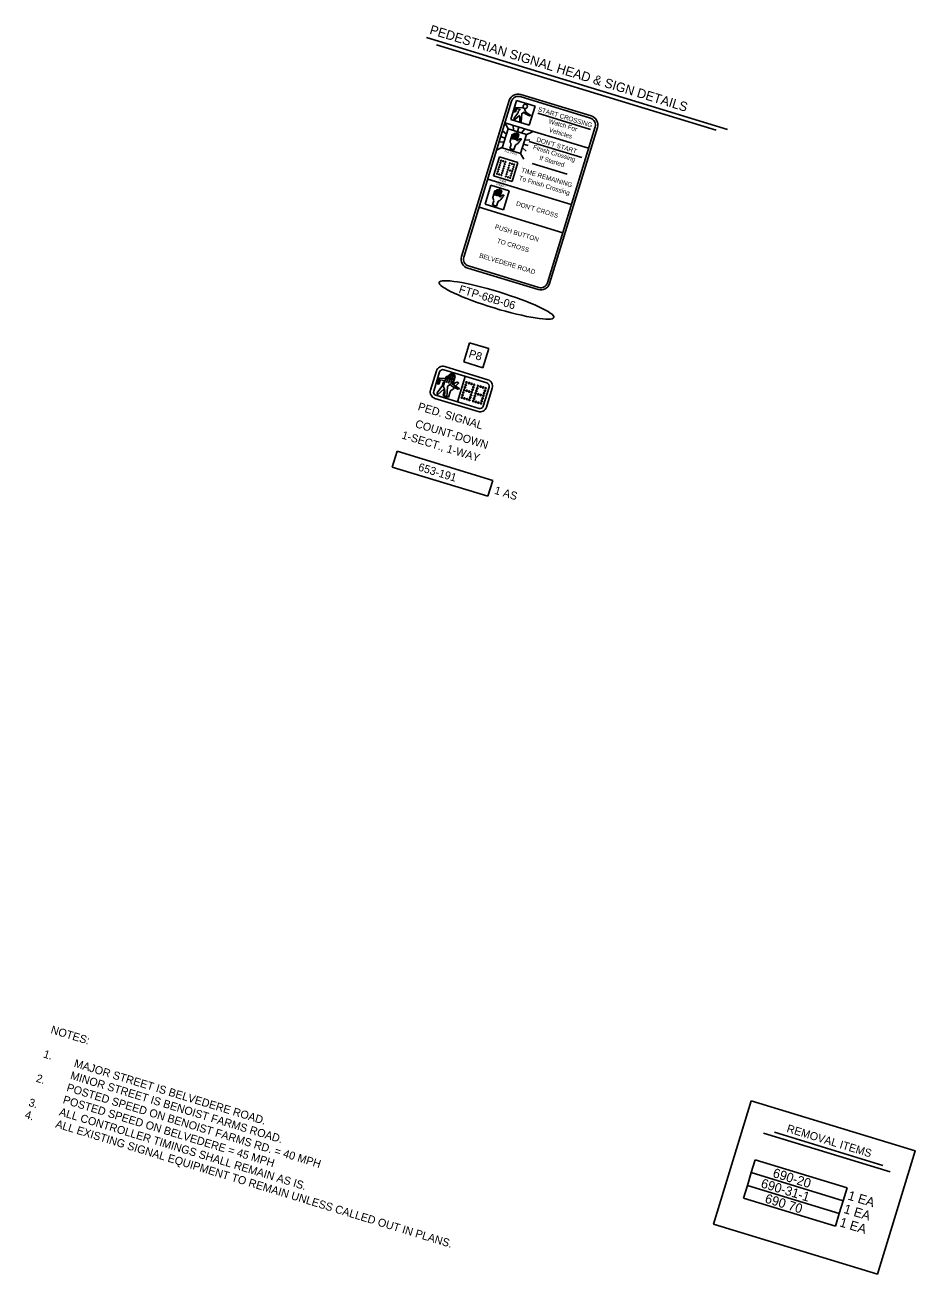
# Model space of a CAD drawing. Extents: x 925415 to 926090, y 857813 to 858332.
import ezdxf

# ---------------------------------------------------------------- set-up
doc = ezdxf.new("R2010")
doc.units = 0
for name, color, linetype in [('PayItem_dp', 7, 'Continuous'), ('PedHead', 7, 'Continuous'), ('SignalHead', 7, 'Continuous'), ('SignalSOP', 7, 'Continuous'), ('SignPanel', 7, 'Continuous'), ('SumBoxLines_dp', 7, 'Continuous'), ('TextMisc', 7, 'Continuous'), ('TextNotes', 7, 'Continuous'), ('TextTables', 7, 'Continuous')]:
    doc.layers.add(name, color=color, linetype=linetype)

msp = doc.modelspace()

# ---------------------------------------------------------------- linework, layer by layer
at = {"layer": 'PayItem_dp'}
msp.add_ellipse((925555.93, 858249.83), major_axis=(17.21, -5.26), ratio=0.138889, dxfattribs=at)
at = {"layer": 'PedHead'}
for p, q in [((925546.11, 858231.24), (925547.87, 858236.97)), ((925547.87, 858236.97), (925553.61, 858235.22)), ((925553.61, 858235.22), (925551.85, 858229.48)), ((925551.85, 858229.48), (925546.11, 858231.24)), ((925546.59, 858226.91), (925544.25, 858219.26))]:
    msp.add_line(p, q, dxfattribs=at)
for points in [[(925537.93, 858228.52), (925536.17, 858222.78)], [(925538.88, 858228.22), (925537.13, 858222.49)], [(925553.04, 858224.94), (925540.13, 858228.89)], [(925540.42, 858229.84), (925553.33, 858225.89)], [(925551.95, 858217.95), (925553.7, 858223.69)], [(925537.5, 858220.28), (925550.41, 858216.33)], [(925537.79, 858221.24), (925550.7, 858217.29)], [(925552.9, 858217.66), (925554.66, 858223.4)]]:
    msp.add_lwpolyline(points, dxfattribs=at)
for points in [[(925539.91, 858221.22), (925540.3, 858222.52), (925540.39, 858222.78), (925540.4, 858223.11), (925540.35, 858223.21), (925540.28, 858223.4), (925540.13, 858223.58), (925540.1, 858223.75), (925540.06, 858224.05), (925540.09, 858224.13), (925540.89, 858226.77), (925541.03, 858226.81), (925541.07, 858226.93), (925541.23, 858226.92), (925541.34, 858226.84), (925541.42, 858226.7), (925541.4, 858226.66), (925541, 858225.07), (925541.64, 858227.17), (925541.78, 858227.34), (925542.02, 858227.3), (925542.1, 858227.28), (925542.23, 858227.03), (925541.57, 858224.89), (925542.44, 858227.3), (925542.57, 858227.47), (925542.66, 858227.49), (925542.89, 858227.42), (925542.94, 858227.32), (925542.91, 858227.2), (925542.24, 858224.73), (925542.93, 858226.99), (925543.09, 858227.1), (925543.21, 858227.11), (925543.38, 858227.1), (925543.47, 858226.99), (925543.55, 858226.84), (925542.85, 858224.54), (925542.82, 858224.47), (925542.89, 858224.4), (925542.98, 858224.42), (925542.98, 858224.42), (925543.56, 858224.95), (925543.84, 858225.03), (925543.85, 858225.07), (925543.94, 858225.09), (925544.04, 858225.14), (925544.16, 858225.14), (925544.43, 858225.06), (925544.53, 858224.99), (925544.51, 858224.91), (925544.5, 858224.87), (925544.49, 858224.84), (925544.47, 858224.8), (925544.05, 858224.38), (925543.19, 858223.35), (925543.02, 858223.19), (925542.77, 858222.93), (925542.62, 858222.85), (925542.39, 858222.76), (925542.26, 858222.63), (925542.03, 858222.28), (925541.55, 858220.71)], [(925542.32, 858226.08), (925541.7, 858226.27), (925538.82, 858226.4), (925538.2, 858224.67), (925538.68, 858224.6), (925539.18, 858225.83), (925540.58, 858225.61), (925540.45, 858225.44), (925540.27, 858225.29), (925539.88, 858224.95), (925539.82, 858224.76), (925539.85, 858224.58), (925539.79, 858224.39), (925539.73, 858224.2), (925539.72, 858224.16), (925538.13, 858221.97), (925538.23, 858221.35), (925540.26, 858223.2), (925540.46, 858222.47), (925540.4, 858220.65), (925541.07, 858220.65), (925541.16, 858222.3), (925541.23, 858223.91), (925542.01, 858224.55), (925542.51, 858223.98), (925544.32, 858223.05), (925544.84, 858223.14), (925542.95, 858224.47), (925542.54, 858225.43), (925542.56, 858225.51), (925542.47, 858225.62), (925542.47, 858225.62)]]:
    msp.add_lwpolyline(points, close=True, dxfattribs=at)
for centre, radius in [((925542.62, 858226.85), 0.87), ((925546.49, 858223.6), 0.2), ((925546.72, 858224.36), 0.2), ((925546.95, 858225.13), 0.2), ((925547.72, 858224.89), 0.2), ((925548.48, 858224.66), 0.2), ((925549.01, 858223.66), 0.2), ((925549.25, 858224.42), 0.2), ((925550.4, 858224.07), 0.2), ((925551.16, 858223.84), 0.2), ((925551.93, 858223.61), 0.2), ((925552.69, 858223.37), 0.2), ((925545.55, 858220.54), 0.2), ((925545.78, 858221.3), 0.2), ((925546.02, 858222.07), 0.2), ((925546.25, 858222.83), 0.2), ((925546.31, 858220.3), 0.2), ((925547.02, 858222.6), 0.2), ((925547.08, 858220.07), 0.2), ((925547.78, 858222.36), 0.2), ((925547.84, 858219.83), 0.2), ((925548.08, 858220.6), 0.2), ((925548.31, 858221.36), 0.2), ((925548.55, 858222.13), 0.2), ((925548.78, 858222.89), 0.2), ((925549.23, 858220.25), 0.2), ((925549.46, 858221.01), 0.2), ((925549.69, 858221.78), 0.2), ((925549.93, 858222.54), 0.2), ((925550.16, 858223.31), 0.2), ((925550.46, 858221.54), 0.2), ((925551.22, 858221.31), 0.2), ((925551.76, 858220.31), 0.2), ((925551.99, 858221.08), 0.2), ((925552.22, 858221.84), 0.2), ((925552.46, 858222.61), 0.2), ((925548.99, 858219.48), 0.2), ((925549.76, 858219.25), 0.2), ((925550.52, 858219.02), 0.2), ((925551.29, 858218.78), 0.2), ((925551.52, 858219.55), 0.2)]:
    msp.add_circle(centre, radius, dxfattribs=at)
for centre, radius, start, end in [((925539.84, 858227.93), 2, 72.9928, 162.9928), ((925539.84, 858227.93), 1, 72.9928, 162.9928), ((925552.75, 858223.98), 1, 342.9928, 72.9928), ((925552.75, 858223.98), 2, 342.9928, 72.9928), ((925538.08, 858222.19), 2, 162.9928, 252.9928), ((925538.08, 858222.19), 1, 162.9928, 252.9928), ((925550.99, 858218.24), 2, 252.9928, 342.9928), ((925550.99, 858218.24), 1, 252.9928, 342.9928)]:
    msp.add_arc(centre, radius, start, end, dxfattribs=at)
at = {"layer": 'SignalHead'}
for p, q in [((925632.31, 857988.08), (925633.48, 857991.91)), ((925633.48, 857991.91), (925661.02, 857983.5)), ((925631.14, 857984.26), (925632.31, 857988.08)), ((925659.86, 857979.67), (925632.31, 857988.08)), ((925632.31, 857988.08), (925659.86, 857979.67)), ((925629.98, 857980.43), (925631.14, 857984.26)), ((925658.69, 857975.85), (925631.14, 857984.26)), ((925631.14, 857984.26), (925658.69, 857975.85)), ((925657.52, 857972.02), (925629.98, 857980.43)), ((925661.02, 857983.5), (925659.86, 857979.67)), ((925659.86, 857979.67), (925658.69, 857975.85)), ((925658.69, 857975.85), (925657.52, 857972.02))]:
    msp.add_line(p, q, dxfattribs=at)
at = {"layer": 'SignalSOP'}
for p, q in [((925635.94, 857999.93), (925673.96, 857988.32)), ((925639.23, 858000.18), (925671.75, 857990.25))]:
    msp.add_line(p, q, dxfattribs=at)
at = {"layer": 'SignPanel'}
for p, q in [((925563.02, 858310.81), (925584.13, 858304.36)), ((925563.22, 858311.47), (925584.34, 858305.02)), ((925545.47, 858262.83), (925559.77, 858309.63)), ((925546.13, 858262.62), (925560.43, 858309.43)), ((925561.98, 858309.62), (925560.24, 858303.92)), ((925558.46, 858302.97), (925583.53, 858295.31)), ((925558.49, 858302.96), (925559.4, 858301.18)), ((925561.03, 858300.68), (925560.91, 858302.22)), ((925568.34, 858305.81), (925584.12, 858300.99)), ((925557.19, 858298.81), (925558.54, 858298.37)), ((925557.71, 858300.53), (925558.9, 858299.52)), ((925559.4, 858301.18), (925564.92, 858299.49)), ((925562.21, 858300.32), (925562.65, 858301.69)), ((925564.92, 858299.49), (925563.18, 858293.79)), ((925563.4, 858299.96), (925564.41, 858301.15)), ((925564.87, 858299.31), (925566.77, 858300.28)), ((925585.51, 858301.77), (925571.21, 858254.96)), ((925586.17, 858301.57), (925571.87, 858254.76)), ((925555.95, 858294.75), (925557.71, 858295.65)), ((925556.67, 858297.11), (925558.2, 858297.23)), ((925563.18, 858293.79), (925557.66, 858295.48)), ((925563.69, 858295.44), (925564.87, 858294.44)), ((925564.04, 858296.6), (925565.4, 858296.16)), ((925564.39, 858297.73), (925565.91, 858297.86)), ((925565.76, 858297.36), (925581.54, 858292.54)), ((925556.82, 858292.73), (925562.34, 858291.04)), ((925562.34, 858291.04), (925560.6, 858285.34)), ((925563.18, 858293.79), (925564.09, 858292.01)), ((925566.63, 858290.75), (925577.12, 858287.54)), ((925553.3, 858286.07), (925578.37, 858278.41)), ((925554.24, 858284.28), (925559.76, 858282.6)), ((925560.6, 858285.34), (925555.08, 858287.03)), ((925559.76, 858282.6), (925558.02, 858276.9)), ((925550.72, 858277.63), (925575.79, 858269.97)), ((925558.02, 858276.9), (925552.5, 858278.58)), ((925568.42, 858252.93), (925547.31, 858259.38)), ((925568.63, 858253.59), (925547.51, 858260.04))]:
    msp.add_line(p, q, dxfattribs=at)
for points in [[(925564.31, 858307.29), (925563.89, 858307.42), (925561.74, 858307.55), (925561.23, 858306.27), (925561.63, 858306.26), (925561.96, 858307.14), (925563.01, 858306.99), (925562.91, 858306.85), (925562.8, 858306.71), (925562.5, 858306.46), (925562.45, 858306.3), (925562.47, 858306.18), (925562.44, 858306.07), (925562.39, 858305.91), (925562.37, 858305.86), (925561.19, 858304.26), (925561.29, 858303.82), (925562.79, 858305.15), (925562.91, 858304.6), (925562.91, 858303.27), (925563.36, 858303.25), (925563.45, 858304.49), (925563.53, 858305.68), (925564.13, 858306.13), (925564.47, 858305.74), (925565.83, 858305.09), (925566.2, 858305.15), (925564.76, 858306.11), (925564.46, 858306.84), (925564.49, 858306.94), (925564.44, 858306.96), (925564.44, 858306.96)], [(925559.93, 858295.23), (925560.22, 858296.18), (925560.3, 858296.45), (925560.25, 858296.64), (925560.28, 858296.74), (925560.21, 858296.88), (925560.08, 858297.04), (925560.06, 858297.16), (925560, 858297.35), (925560.03, 858297.45), (925560.63, 858299.41), (925560.77, 858299.48), (925560.77, 858299.48), (925560.94, 858299.48), (925560.98, 858299.42), (925561.09, 858299.38), (925561.07, 858299.33), (925560.7, 858298.12), (925561.18, 858299.7), (925561.34, 858299.83), (925561.5, 858299.78), (925561.55, 858299.76), (925561.67, 858299.61), (925561.17, 858297.97), (925561.78, 858299.75), (925561.88, 858299.89), (925562, 858299.91), (925562.16, 858299.86), (925562.19, 858299.8), (925562.16, 858299.69), (925561.67, 858297.88), (925562.18, 858299.57), (925562.25, 858299.6), (925562.37, 858299.63), (925562.55, 858299.63), (925562.57, 858299.51), (925562.66, 858299.42), (925562.14, 858297.73), (925562.11, 858297.63), (925562.11, 858297.63), (925562.21, 858297.6), (925562.21, 858297.6), (925562.69, 858298.03), (925562.83, 858298.1), (925562.85, 858298.15), (925562.91, 858298.19), (925563.02, 858298.16), (925563.09, 858298.19), (925563.3, 858298.13), (925563.34, 858298.06), (925563.34, 858298.06), (925563.32, 858298.01), (925563.3, 858297.96), (925563.29, 858297.9), (925563.03, 858297.63), (925562.39, 858296.85), (925562.29, 858296.71), (925562.07, 858296.54), (925561.93, 858296.47), (925561.74, 858296.41), (925561.71, 858296.31), (925561.52, 858296.08), (925561.15, 858294.86)], [(925554.77, 858278.34), (925555.06, 858279.29), (925555.14, 858279.55), (925555.09, 858279.74), (925555.12, 858279.85), (925555.05, 858279.99), (925554.92, 858280.14), (925554.9, 858280.26), (925554.84, 858280.45), (925554.87, 858280.56), (925555.47, 858282.51), (925555.61, 858282.59), (925555.61, 858282.59), (925555.78, 858282.59), (925555.82, 858282.52), (925555.93, 858282.49), (925555.91, 858282.44), (925555.54, 858281.22), (925556.02, 858282.81), (925556.18, 858282.93), (925556.33, 858282.88), (925556.39, 858282.87), (925556.51, 858282.71), (925556.01, 858281.08), (925556.61, 858282.86), (925556.72, 858283), (925556.84, 858283.02), (925557, 858282.97), (925557.03, 858282.9), (925557, 858282.8), (925556.5, 858280.99), (925557.02, 858282.67), (925557.09, 858282.71), (925557.21, 858282.73), (925557.39, 858282.74), (925557.41, 858282.61), (925557.5, 858282.53), (925556.98, 858280.84), (925556.95, 858280.73), (925556.95, 858280.73), (925557.05, 858280.7), (925557.05, 858280.7), (925557.53, 858281.13), (925557.67, 858281.21), (925557.69, 858281.26), (925557.75, 858281.3), (925557.86, 858281.26), (925557.93, 858281.3), (925558.14, 858281.24), (925558.18, 858281.17), (925558.18, 858281.17), (925558.16, 858281.11), (925558.14, 858281.06), (925558.13, 858281.01), (925557.87, 858280.74), (925557.23, 858279.96), (925557.13, 858279.81), (925556.91, 858279.65), (925556.77, 858279.58), (925556.58, 858279.52), (925556.54, 858279.41), (925556.36, 858279.18), (925555.99, 858277.97)]]:
    msp.add_lwpolyline(points, close=True, dxfattribs=at)
for points in [[(925567.5, 858307.94), (925561.98, 858309.62)], [(925565.76, 858302.24), (925567.5, 858307.94)], [(925560.24, 858303.92), (925565.76, 858302.24)], [(925559.4, 858301.18), (925557.66, 858295.48)], [(925556.82, 858292.73), (925555.08, 858287.03)], [(925554.24, 858284.28), (925552.5, 858278.58)]]:
    msp.add_lwpolyline(points, dxfattribs=at)
for centre, radius in [((925564.55, 858307.89), 0.648), ((925557.1, 858290.96), 0.138), ((925557.31, 858291.62), 0.138), ((925557.97, 858291.42), 0.138), ((925558.63, 858291.22), 0.138), ((925556.1, 858287.66), 0.138), ((925556.3, 858288.32), 0.138), ((925556.5, 858288.98), 0.138), ((925556.7, 858289.64), 0.138), ((925556.76, 858287.46), 0.138), ((925556.9, 858290.3), 0.138), ((925557.42, 858287.26), 0.138), ((925557.62, 858287.92), 0.138), ((925557.82, 858288.58), 0.138), ((925558.02, 858289.24), 0.138), ((925558.22, 858289.9), 0.138), ((925558.42, 858290.56), 0.138), ((925558.94, 858287.51), 0.138), ((925559.14, 858288.17), 0.138), ((925559.34, 858288.83), 0.138), ((925559.54, 858289.49), 0.138), ((925559.74, 858290.15), 0.138), ((925559.94, 858290.81), 0.138), ((925560, 858288.63), 0.138), ((925560.26, 858287.11), 0.138), ((925560.46, 858287.77), 0.138), ((925560.6, 858290.61), 0.138), ((925560.66, 858288.43), 0.138), ((925560.86, 858289.09), 0.138), ((925561.06, 858289.75), 0.138), ((925561.26, 858290.41), 0.138), ((925558.74, 858286.85), 0.138), ((925559.4, 858286.65), 0.138), ((925560.06, 858286.45), 0.138)]:
    msp.add_circle(centre, radius, dxfattribs=at)
for centre, radius, start, end in [((925562.41, 858308.83), 2.76, 73.0133, 163.0133), ((925562.41, 858308.83), 2.07, 73.0133, 163.0133), ((925583.53, 858302.38), 2.07, 343.0133, 73.0133), ((925583.53, 858302.38), 2.76, 343.0133, 73.0133), ((925548.11, 858262.02), 2.76, 163.0133, 253.0133), ((925548.11, 858262.02), 2.07, 163.0133, 253.0133), ((925569.23, 858255.57), 2.76, 253.0133, 343.0133), ((925569.23, 858255.57), 2.07, 253.0133, 343.0133)]:
    msp.add_arc(centre, radius, start, end, dxfattribs=at)
at = {"layer": 'SumBoxLines_dp'}
msp.add_lwpolyline([(925632.28, 858009.63), (925681.39, 857994.64), (925670.11, 857957.68), (925621, 857972.67)], close=True, dxfattribs=at)
at = {"layer": 'TextNotes'}
for p, q in [((925524.69, 858199.69), (925526.15, 858204.47)), ((925526.15, 858204.47), (925554.84, 858195.71)), ((925553.38, 858190.93), (925524.69, 858199.69)), ((925554.84, 858195.71), (925553.38, 858190.93))]:
    msp.add_line(p, q, dxfattribs=at)
at = {"layer": 'TextTables'}
for p, q in [((925534.94, 858328.5), (925625.23, 858300.94)), ((925537.91, 858326.34), (925621.75, 858300.74))]:
    msp.add_line(p, q, dxfattribs=at)

# ---------------------------------------------------------------- texts
at = {"layer": 'PayItem_dp'}
msp.add_text('FTP-68B-06', height=2.4, rotation=343.0133, dxfattribs=at).set_placement((925544.47, 858252.06))
at = {"layer": 'PedHead'}
for s, rotation, p in [('P8', 343.0133, (925547.43, 858232.72)), ('PED. SIGNAL', 342.9928, (925532.19, 858216.88)), ('COUNT-DOWN', 342.9928, (925531.38, 858211.7)), ('1-SECT., 1-WAY', 342.9928, (925527.33, 858208.33)), (' 1 AS ', 343.0214, (925554.27, 858192.01))]:
    msp.add_text(s, height=2.4, rotation=rotation, dxfattribs=at).set_placement(p)
at = {"layer": 'SignalHead'}
for s, p in [('690-20', (925638.54, 857986.81)), ('690-31-1', (925634.99, 857983.71)), ('690 70', (925636.2, 857979.16))]:
    msp.add_text(s, height=2.8, rotation=343.0214, dxfattribs=at).set_placement(p)
at = {"layer": 'SignalSOP'}
for s, height, p in [('REMOVAL ITEMS', 2.4, (925642.74, 858000.33)), ('1 EA', 2.8, (925661.03, 857980.06)), ('1 EA', 2.8, (925659.8, 857976.05)), ('1 EA', 2.8, (925658.57, 857972.03))]:
    msp.add_text(s, height=height, rotation=343.0214, dxfattribs=at).set_placement(p)
at = {"layer": 'SignPanel'}
for s, height, p in [('START CROSSING', 1.3801, (925568.25, 858306.46)), ('Watch For', 1.38, (925571.47, 858302.88)), ("DON'T START", 1.3801, (925567.8, 858297.36)), ('Vehicles', 1.38, (925571.51, 858300.27)), ('FLASHING', 0.552, (925558.33, 858294.28)), ('Finish Crossing', 1.3801, (925566.79, 858295.07)), ('If Started', 1.38, (925568.68, 858291.9)), ('TIME REMAINING', 1.3801, (925563.24, 858288.22)), ('STEADY', 0.552, (925555.69, 858284.35)), ('TIMER', 0.552, (925556.45, 858285.62)), ('To Finish Crossing', 1.3801, (925562.52, 858285.84)), ("DON'T CROSS", 1.3801, (925561.7, 858278.19)), ('PUSH BUTTON', 1.3801, (925555.33, 858271.23)), ('TO CROSS', 1.38, (925555.96, 858266.99)), ('BELVEDERE ROAD', 1.3801, (925550.66, 858262.61))]:
    msp.add_text(s, height=height, rotation=343.0133, dxfattribs=at).set_placement(p)
at = {"layer": 'TextMisc'}
for s, p in [('NOTES:', (925422.14, 858029.95)), ('1.', (925419.92, 858022.68)), ('MAJOR STREET IS BELVEDERE ROAD.', (925429.11, 858019.88)), ('2.', (925417.71, 858015.41)), ('MINOR STREET IS BENOIST FARMS ROAD.', (925428, 858016.24)), ('POSTED SPEED ON BENOIST FARMS RD. = 40 MPH', (925426.89, 858012.61)), ('3.', (925415.49, 858008.14)), ('POSTED SPEED ON BELVEDERE = 45 MPH', (925425.78, 858008.97)), ('4. ', (925414.38, 858004.5)), ('ALL CONTROLLER TIMINGS SHALL REMAIN AS IS.', (925424.67, 858005.34)), ('ALL EXISTING SIGNAL EQUIPMENT TO REMAIN UNLESS CALLED OUT IN PLANS.', (925423.57, 858001.7))]:
    msp.add_text(s, height=2.4, rotation=343.0441, dxfattribs=at).set_placement(p)
at = {"layer": 'TextNotes'}
msp.add_text('653-191', height=2.4, rotation=343.0214, dxfattribs=at).set_placement((925532.28, 858198.71))
at = {"layer": 'TextTables'}
msp.add_text('PEDESTRIAN SIGNAL HEAD & SIGN DETAILS', height=2.8001, rotation=343.0441, dxfattribs=at).set_placement((925535.7, 858329.71))

doc.saveas('drawing.dxf')
